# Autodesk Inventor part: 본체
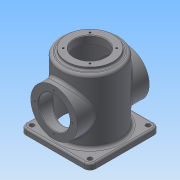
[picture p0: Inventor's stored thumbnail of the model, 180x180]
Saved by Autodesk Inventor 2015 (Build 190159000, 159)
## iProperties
Created: 2015-10
Part Number: 본체
Material: Generic
Document SubType Name: Modeling
Designer: 602-22
Density: 1 g/cm^3
Appearance: Default
Author: 602-22
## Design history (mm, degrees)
sketch "Sketch1"
  geometry: L1 (60, -60)-(-60, -60); L2 (-60, -60)-(-60, 60); L3 (-60, 60)-(60, 60); L4 (60, 60)-(60, -60); L5 (0, -60)-(0, 60); 2 further points
  constraints: 10 end point, 3 midpoint, 2 parallel, 1 coincident, 1 horizontal, 1 perpendicular
  dimensions: "d0" = 120 distance of L2.end L3.end; "d1" = 120 distance of L1.end L2.end
extrude "Extrusion1" new body sketch "Sketch1" distance "d2" = 10; taper "d3" = 0 deg
sketch "Sketch2"
  geometry: C1 r 50 at (0, 0); 1 further point
  constraints: 1 centre point, 1 coincident
  dimensions: "d4" = 100 diameter of C1
extrude "Extrusion2" join sketch "Sketch2" distance "d5" = 110; taper "d6" = 0 deg
workplane "Work Plane1"
sketch "Sketch4"
  geometry: L1 (60, 0)-(60, 60); C1 r 40 at (60, 60)
  constraints: 2 end point, 1 centre point, 1 coincident, 1 vertical
  dimensions: "d15" = 60 distance of L1.start L1.end; "d16" = 80 diameter of C1
extrude "Extrusion3" join sketch "Sketch4" stored distance "d17" = 124; taper "d18" = 0 deg
sketch "Sketch5"
  geometry: C1 r 40 at (0, 0) reference; C2 r 27 at (0, 0); 1 further point
  constraints: 1 centre point, 1 coincident
  dimensions: "d19" = 54 diameter of C2
extrude "Extrusion4" cut sketch "Sketch5" stored distance "d20" = 124; taper "d21" = 0 deg
workplane "Work Plane2"
sketch "Sketch6"
  geometry: C1 r 40 at (0, 0); 1 further point
  constraints: 1 centre point, 1 coincident
  dimensions: "d23" = 80 diameter of C1
extrude "Extrusion5" join sketch "Sketch6" stored distance "d24" = 124; taper "d25" = 0 deg
sketch "Sketch7"
  geometry: C1 r 27 at (0, 0); 1 further point
  constraints: 1 centre point, 1 coincident
  dimensions: "d26" = 54 diameter of C1
extrude "Extrusion6" cut sketch "Sketch7" distance "d27" = 13; taper "d28" = 0 deg
sketch "Sketch8"
  geometry: C1 r 45 at (0, 0); 1 further point
  constraints: 1 centre point, 1 coincident
  dimensions: "d29" = 90 diameter of C1
extrude "Extrusion7" cut sketch "Sketch8" distance "d30" = 112; taper "d31" = 0 deg
chamfer "Chamfer2" distance "d35" = 1; stored, may be unused: second distance "d36" = 2, angle "d37" = 45 deg
chamfer "Chamfer3" distance "d38" = 3; stored, may be unused: second distance "d39" = 2, angle "d40" = 45 deg
fillet "Fillet1" dims "d41" = 10, "d42" = 5, "d70" = 3
sketch "Sketch9"
  geometry: L1 (22.981, -22.981)-(-22.981, 22.981); L2 (22.981, 22.981)-(-22.981, -22.981); L3 (0, 0)-(32.5, 0); A1 r 32.5 centre (0, 0) between (22.981, -22.981) and (-22.981, 22.981); 1 further point
  constraints: 6 end point, 5 point on circle, 2 coincident, 2 midpoint, 1 centre point, 1 horizontal
  dimensions: "d44" = 65 diameter of A1; "d45" = 45 deg angle of L3 L2; "d46" = 90 deg angle of L1 L2
hole "Hole1" sketch "Sketch9" at (-22.981, 22.981), (22.981, 22.981), (-22.981, -22.981), (22.981, -22.981) diameter "d47" = 3.242; stored, may be unused: countersink angle "d51" = 90 deg, drill point angle "d53" = 118 deg; dims "d48" = 8, "d49" = 4, "d50" = 2, "d52" = 10
sketch "Sketch10"
  geometry: L1 (0, 32.5)-(0, -32.5); L2 (-32.5, 0)-(32.5, 0); C1 r 28 at (0, 0) reference; A1 r 32.5 centre (0, 0) between (-32.5, 0) and (0, 32.5); 2 further points
  constraints: 4 end point, 4 point on circle, 2 coincident, 2 midpoint, 1 centre point, 1 horizontal, 1 vertical
  dimensions: "d54" = 65 diameter of A1
hole "Hole2" sketch "Sketch10" at (0, 32.5), (0, -32.5), (32.5, 0), (-32.5, 0) diameter "d55" = 3.242; stored, may be unused: countersink angle "d59" = 90 deg, drill point angle "d61" = 118 deg; dims "d56" = 8, "d57" = 4, "d58" = 2, "d60" = 10
sketch "Sketch11"
  geometry: L1 (0, 32.5)-(0, -32.5); L2 (32.5, 0)-(-32.5, 0); C1 r 28 at (0, 0) reference; A1 r 32.5 centre (0, 0) between (0, 32.5) and (0, -32.5); 2 further points
  constraints: 4 end point, 4 point on circle, 2 coincident, 2 midpoint, 1 centre point, 1 horizontal, 1 vertical
  dimensions: "d62" = 65 diameter of A1
hole "Hole3" sketch "Sketch11" at (0, 32.5), (32.5, 0), (0, -32.5), (-32.5, 0) diameter "d63" = 3.242; stored, may be unused: countersink angle "d67" = 90 deg, drill point angle "d69" = 118 deg; dims "d64" = 8, "d65" = 4, "d66" = 2, "d68" = 10
sketch "Sketch12"
  geometry: L1 (-50, 50)-(50, 50); L2 (50, 50)-(50, -50); L3 (50, -50)-(-50, -50); L4 (-50, -50)-(-50, 50); L5 (0, 50)-(0, -50); 2 further points
  constraints: 10 end point, 3 midpoint, 2 parallel, 1 coincident, 1 horizontal, 1 perpendicular
  dimensions: "d71" = 100 distance of L2.end L3.end; "d72" = 100 distance of L1.end L2.end
hole "Hole4" sketch "Sketch12" at (-50, 50), (50, 50), (50, -50), (-50, -50) diameter "d73" = 8; stored, may be unused: countersink angle "d77" = 90 deg, drill point angle "d79" = 118 deg; dims "d74" = 8, "d75" = 4, "d76" = 2, "d78" = 10
workplane "Work Plane7"
  workplane "Work Plane6"
sketch "Sketch18"
  geometry: L1 (50, 0)-(50, 70); 1 further point
  constraints: 2 end point, 1 coincident, 1 vertical, 1 other
  dimensions: "d84" = 70 distance of L1.start L1.end
emboss "Emboss1" sketch "Sketch18" dims "d0" = 120, "d1" = 120, "d85" = 0.5, "d86" = 0
body "Solid1"
other parameters: "d22" = 5, "d83" = 50.5
